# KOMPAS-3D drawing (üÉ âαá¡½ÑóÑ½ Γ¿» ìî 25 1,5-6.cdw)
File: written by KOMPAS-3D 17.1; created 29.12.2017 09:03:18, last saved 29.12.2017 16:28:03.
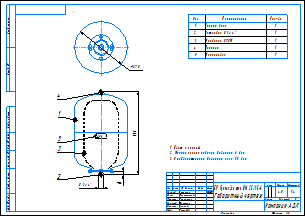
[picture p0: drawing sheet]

Sheet 1: A3, landscape, title-block layout from C:\Лощинин\GRAPHIC.LYT style 1

Title block, sheet 1: name: БР Гранлевел тип НМ 25/1,5-6 / Габаритный чертеж; mass: 4,0; sheets: 1; sheet format: A3; stored path: K:\АП\20_PKO\02_Насосное направление\Разработка\04_Проекты разные\Баки\КД действующая\Баки Flexcon R\Компас\Чертежи\БР Гранлевел тип НМ 25 1,5-6.cdw; drawn by: Лощинин; checked by: Хантимеров; drawn by, date: 29.12.2017

Views: Вид 1, Снизу
Referenced files in \\Fsk1\files\АП\20_PKO\02_Насосное направление\Разработка\04_Проекты разные\Баки\КД действующая\Баки Flexcon R\Компас\: 25 литров.a3d
Referenced files in C:\Лощинин\: GRAPHIC.LYT
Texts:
  IvAn
  ADL
  Цвет: красный
  Максимальное рабочее давление: 6 бар
  Предварительное давление газа: 1,5 бар
  ACAD_ISO03W100_RGB_223_127_255_SC_1_THICK_0.05
  ACAD_ISO03W100_RGB_223_127_255_SC_0.063_THICK_0.05
  Лит-Масса-Масштаб
  Материал-Предприятие
  Масштаб
  Изм.
  Лист
  № докум.
  Подп.
  Дата
  Лит.
  Разраб.
  Пров.
  Т.контр.
  Курлыкина
  Листов
  Нач.отд.
  Щетинин
  Н.контр.
  Долгов
  Утв.
  Рашидов
  Компания АДЛ
  Изменение
  Номер документа
  Подпись
  Обозначение документа
  Наименование изделия
  Масса изделия по ГОСТ 2.109-73
  Порядковый номер листа
  Общее количество листов в документе
  Характер работы, выполненной лицом, подписавшим документ
  Наименование или индекс предприятия, выпускающего документ
  Инв. № подл.
  Подп. и дата
  Взам. инв. №
  Инв. № дубл.
  Инвентарный номер подлинника по ГОСТ 2.501-68
  Подпись принявшего подлинник в отдел технической документации
  Инвентарный номер подлинника, взамен которого выпущен данный подлинник
  Инвентарный номер дубликата по ГОСТ 2.502-68
  Подпись принявшего дубликат в отдел технической документации
  Справ. №
  Перв. примен.
  Обозначение документа, взамен или на основании которого выпущен данный документ
  Обозначение документа, в котором впервые записан данный документ
  Подпись лица, копировавшего чертеж
  Обозначение формата листа
Dimensions and other numbers on the sheet: 290; 1:4; 1; 4,0; 29.12.2017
